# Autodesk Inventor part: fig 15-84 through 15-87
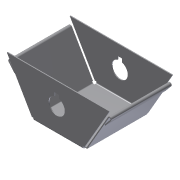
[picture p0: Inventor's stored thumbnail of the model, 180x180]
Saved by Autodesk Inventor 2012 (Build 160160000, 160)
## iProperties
Shininess: 50.0
Angle Display Precision: 2
Document Length Units: 11269
Document Angle Units: 11279
Document Time Units: 11290
Document Mass Units: 11283
Document Length Units Precision: 3
Document Angle Units Precision: 2
Created: 2002-04
Part Number: fig 15-84 through 15-87
Document SubType Name: Sheet Metal
Density: 1 g/cm^3
Sheet Metal Rule: Default
Material: Default
Density: 0.0
Volumn: 0.0
Area: 0.0
PropertySet Name: Model Information
Control State: 0
Master: False
Checked Out: False
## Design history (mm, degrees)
node "Face1"
  sketch "Sketch1"
    geometry: L1 (-24.824, 17.882)-(5.529, 17.882); L2 (5.529, 17.882)-(5.529, -17.529); L3 (5.529, -17.529)-(-24.824, -17.529); L4 (-24.824, -17.529)-(-24.824, 17.882)
    constraints: 8 end point, 2 parallel, 1 horizontal, 1 perpendicular
node "Flange2"
node "Flange3"
node "Flange4"
node "Flange5"
feature "Corner1" dims "d45" = 0.5 (= Thickness), "d46" = 0, "d81" = 2 (= CornerReliefSize), "Thickness" = 0.5, "TransitionRadius" = 0.5 (= BendRadius)
feature "Corner2" dims "d47" = 0.5 (= Thickness), "d48" = 0, "d82" = 2 (= CornerReliefSize), "Thickness" = 0.5, "TransitionRadius" = 0.5 (= BendRadius)
feature "Corner3" dims "d49" = 0.5 (= Thickness), "d50" = 0, "d83" = 2 (= CornerReliefSize), "Thickness" = 0.5, "TransitionRadius" = 0.5 (= BendRadius)
feature "Corner4" dims "d51" = 0.5 (= Thickness), "d52" = 0, "d84" = 2 (= CornerReliefSize), "Thickness" = 0.5, "TransitionRadius" = 0.5 (= BendRadius)
feature "Hem1" dims "d53" = 0.5 (= BendRadius), "d54" = 190 deg, "d55" = 0.5 (= BendRadius), "d56" = 0.5 (= d55), "d75" = 0.5 (= BendReliefWidth), "d76" = 0.25 (= BendReliefDepth), "d77" = 1 (= MinimumRemnant), "SeamGap" = 0.01, "Thickness" = 0.5, "MinimumRemnant" = 1 (= 2 x Thickness), "BendReliefWidth" = 0.5 (= Thickness)
feature "Hem2" dims "d57" = 0.5 (= BendRadius), "d58" = 190 deg, "d59" = 0.5 (= BendRadius), "d60" = 0.5 (= d59), "d78" = 0.5 (= BendReliefWidth), "d79" = 0.25 (= BendReliefDepth), "d80" = 1 (= MinimumRemnant), "SeamGap" = 0.01, "Thickness" = 0.5, "MinimumRemnant" = 1 (= 2 x Thickness), "BendReliefWidth" = 0.5 (= Thickness)
sketch "Sketch12"
  geometry: L1 (28.924, -7.829)-(28.924, -5.94); L2 (28.924, -5.94)-(26.464, -5.94); L3 (26.464, -5.94)-(26.464, -7.829); A1 r 4.497 centre (27.694, -12.155) between (26.464, -7.829) and (28.924, -7.829)
  constraints: 6 end point, 2 point on circle, 1 centre point, 1 parallel
cut "Cut1" sketch "Sketch12" dims "d61" = 0.5 (= Thickness), "d62" = 0
body "Solid1"
face "Plate1" dims "Thickness" = 0.5
sketch "Sketch6"
  geometry: L1 (30.412, 0)-(5, 0); L2 (5, 0)-(5, 25); L3 (5, 25)-(30.412, 25); L4 (30.412, 25)-(30.412, 0)
  constraints: 8 end point
face "Plate7" dims "d21" = 5, "d22" = 5, "d24" = 25, "d25" = 60 deg, "d26" = 0.5 (= BendRadius), "Thickness" = 0.5, "MinimumRemnant" = 1 (= 2 x Thickness), "BendReliefWidth" = 0.5 (= Thickness)
bend "Bend6" dims "d23" = 0.5 (= BendRadius), "d24" = 25, "d25" = 60 deg, "d26" = 0.5 (= BendRadius), "d63" = 0.5 (= BendReliefWidth), "d64" = 0.25 (= BendReliefDepth), "d65" = 1 (= MinimumRemnant), "SeamGap" = 0.01, "Thickness" = 0.5, "MinimumRemnant" = 1 (= 2 x Thickness), "BendReliefWidth" = 0.5 (= Thickness)
sketch "Sketch7"
  geometry: L1 (25.353, 0)-(5, 0); L2 (5, 0)-(5, 25); L3 (5, 25)-(25.353, 25); L4 (25.353, 25)-(25.353, 0)
  constraints: 8 end point
face "Plate8" dims "d27" = 5, "d28" = 5, "d30" = 25, "d31" = 90 deg, "d32" = 0.5 (= BendRadius), "Thickness" = 0.5, "MinimumRemnant" = 1 (= 2 x Thickness), "BendReliefWidth" = 0.5 (= Thickness)
bend "Bend7" dims "d29" = 0.5 (= BendRadius), "d30" = 25, "d31" = 90 deg, "d32" = 0.5 (= BendRadius), "d66" = 0.5 (= BendReliefWidth), "d67" = 0.25 (= BendReliefDepth), "d68" = 1 (= MinimumRemnant), "SeamGap" = 0.01, "Thickness" = 0.5, "MinimumRemnant" = 1 (= 2 x Thickness), "BendReliefWidth" = 0.5 (= Thickness)
sketch "Sketch8"
  geometry: L1 (5, 0)-(30.412, 0); L2 (30.412, 0)-(30.412, 25); L3 (30.412, 25)-(5, 25); L4 (5, 25)-(5, 0)
  constraints: 8 end point
face "Plate9" dims "d33" = 5, "d34" = 5, "d36" = 25, "d37" = 60 deg, "d38" = 0.5 (= BendRadius), "Thickness" = 0.5, "MinimumRemnant" = 1 (= 2 x Thickness), "BendReliefWidth" = 0.5 (= Thickness)
bend "Bend8" dims "d35" = 0.5 (= BendRadius), "d36" = 25, "d37" = 60 deg, "d38" = 0.5 (= BendRadius), "d69" = 0.5 (= BendReliefWidth), "d70" = 0.25 (= BendReliefDepth), "d71" = 1 (= MinimumRemnant), "SeamGap" = 0.01, "Thickness" = 0.5, "MinimumRemnant" = 1 (= 2 x Thickness), "BendReliefWidth" = 0.5 (= Thickness)
sketch "Sketch9"
  geometry: L1 (5, 0)-(25.353, 0); L2 (25.353, 0)-(25.353, 25); L3 (25.353, 25)-(5, 25); L4 (5, 25)-(5, 0)
  constraints: 8 end point
face "Plate10" dims "d39" = 5, "d40" = 5, "d42" = 25, "d43" = 90 deg, "d44" = 0.5 (= BendRadius), "Thickness" = 0.5, "MinimumRemnant" = 1 (= 2 x Thickness), "BendReliefWidth" = 0.5 (= Thickness)
bend "Bend9" dims "d41" = 0.5 (= BendRadius), "d42" = 25, "d43" = 90 deg, "d44" = 0.5 (= BendRadius), "d72" = 0.5 (= BendReliefWidth), "d73" = 0.25 (= BendReliefDepth), "d74" = 1 (= MinimumRemnant), "SeamGap" = 0.01, "Thickness" = 0.5, "MinimumRemnant" = 1 (= 2 x Thickness), "BendReliefWidth" = 0.5 (= Thickness)
sketch "Sketch10"
  geometry: L1 (0.433, 0.25)-(0, 0); L2 (-0.816, -0.571)-(2.395, -4.398); L3 (2.395, -4.398)-(2.012, -4.719); L4 (2.012, -4.719)-(-1.199, -0.893); A1 r 0.5 centre (-0.433, -0.25) between (0, 0) and (-0.816, -0.571); A2 r 1 centre (-0.433, -0.25) between (0.433, 0.25) and (-1.199, -0.893)
  constraints: 8 end point, 4 point on circle
sketch "Sketch11"
  geometry: L1 (0.433, 0.25)-(0, 0); L2 (-0.816, -0.571)-(2.395, -4.398); L3 (2.395, -4.398)-(2.012, -4.719); L4 (2.012, -4.719)-(-1.199, -0.893); A1 r 0.5 centre (-0.433, -0.25) between (0, 0) and (-0.816, -0.571); A2 r 1 centre (-0.433, -0.25) between (0.433, 0.25) and (-1.199, -0.893)
  constraints: 8 end point, 4 point on circle
node "FlatPattern"
feature "FlatPatternExtrusion2" dims "d0" = 0.5 (derived)
other parameters: "BendRadius" = 0.5 (= Thickness), "BendReliefDepth" = 0.25 (= 0.5 x Thickness), "CornerReliefSize" = 2 (= 4 x Thickness), "d0" = 0.5 (= BendRadius), "d4" = 0.5 (= BendRadius), "JacobiRadiusSize" = 0.5 (= Thickness), "GapSize" = 0.5 (= Thickness)
